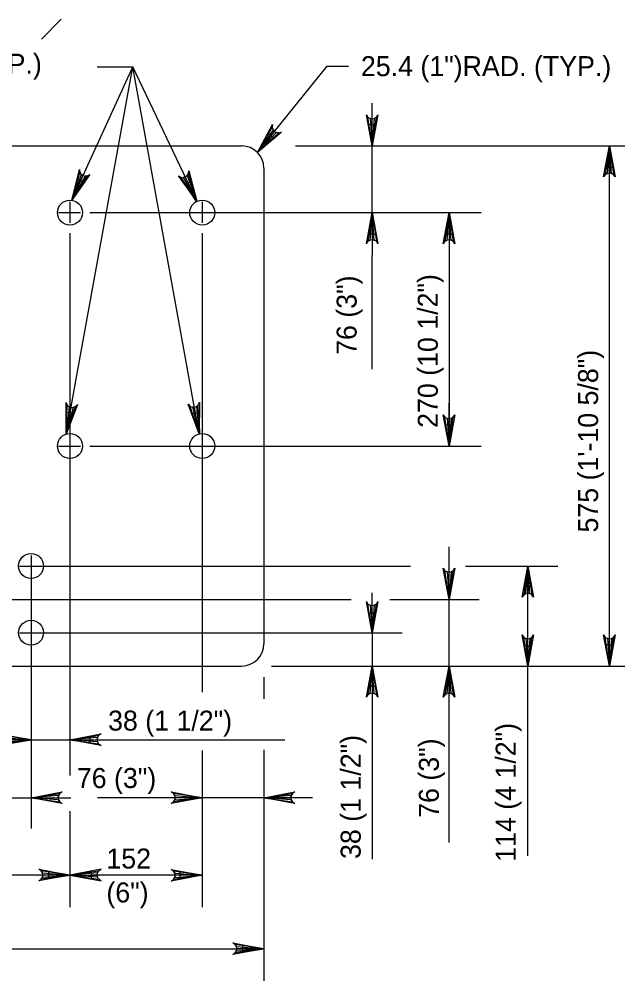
# Model space of a CAD drawing. Extents: x 0 to 36.3, y -66 to 0.
# Drawn here: x 16.77 to 20.36, y -15.09 to -9.32 of the extents above; entities that cross this region are included whole.
import ezdxf

# ---------------------------------------------------------------- set-up
doc = ezdxf.new("R2010")
doc.units = 0
doc.layers.add('2', color=7, linetype='Continuous')
doc.layers.add('3', color=7, linetype='Continuous')

msp = doc.modelspace()

# ---------------------------------------------------------------- linework, layer by layer
at = {"layer": '2'}
for p, q in [((15.0717, -10.0812), (18.1016, -10.0812)), ((18.2348, -10.2145), (18.2348, -13.0677)), ((17.0717, -10.4173), (17.0717, -10.5422)), ((17.865, -10.4173), (17.865, -10.5422)), ((17.0023, -10.4812), (17.1356, -10.4812)), ((17.7956, -10.4812), (17.9289, -10.4812)), ((17.0717, -11.8173), (17.0717, -11.9422)), ((17.865, -11.8173), (17.865, -11.9422)), ((17.0023, -11.8812), (17.1356, -11.8812)), ((17.7956, -11.8812), (17.9289, -11.8812)), ((16.8384, -12.5372), (16.8384, -12.662)), ((16.7691, -12.601), (16.9023, -12.601)), ((16.8384, -12.9372), (16.8384, -13.062)), ((16.7691, -13.001), (16.9023, -13.001))]:
    msp.add_line(p, q, dxfattribs=at)
for centre in [(17.0718, -10.4812), (17.865, -10.4812), (17.0718, -11.8812), (17.865, -11.8812), (16.8385, -12.601), (16.8385, -13.001)]:
    msp.add_circle(centre, 0.075, dxfattribs=at)
for centre, start, end in [((18.1015, -10.2145), 0, 90), ((18.1015, -13.0677), 270, 0)]:
    msp.add_arc(centre, 0.1333, start, end, dxfattribs=at)
at = {"layer": '3'}
for p, q in [((16.9003, -9.4406), (17.0195, -9.3214)), ((17.0498, -11.8094), (17.449, -9.6074)), ((17.0822, -10.4069), (17.449, -9.6074)), ((17.2344, -9.6074), (17.449, -9.6074)), ((17.8336, -10.4131), (17.449, -9.6074)), ((17.8476, -11.8082), (17.449, -9.6074)), ((18.1962, -10.1207), (18.6149, -9.6036)), ((18.6149, -9.6036), (18.743, -9.6036)), ((18.8845, -10.5177), (18.8845, -9.8251)), ((18.4239, -10.0812), (19.0766, -10.0812)), ((18.7894, -10.0812), (20.4997, -10.0812)), ((20.3077, -13.201), (20.3077, -10.0812)), ((17.1916, -10.4812), (19.5383, -10.4812)), ((19.3462, -10.4812), (19.3462, -11.8812)), ((17.0717, -10.6055), (17.0717, -13.8564)), ((17.865, -10.6055), (17.865, -13.3579)), ((18.8845, -10.6092), (18.8845, -10.7373)), ((18.8845, -11.4203), (18.8845, -10.7377)), ((19.3462, -11.7532), (19.3462, -11.6251)), ((17.1916, -11.8812), (19.5383, -11.8812)), ((19.3462, -14.2584), (19.3462, -12.486)), ((16.8384, -12.5522), (16.8384, -14.1747)), ((16.9009, -12.601), (19.1153, -12.601)), ((19.4442, -12.601), (19.9982, -12.601)), ((19.8182, -14.3397), (19.8182, -12.601)), ((16.5009, -12.801), (18.7591, -12.801)), ((18.8845, -13.001), (18.8845, -12.761)), ((18.9901, -12.801), (19.5262, -12.801)), ((16.9009, -13.001), (19.0645, -13.001)), ((18.8845, -13.001), (18.8845, -14.3592)), ((15.0717, -13.201), (18.1016, -13.201)), ((18.2805, -13.201), (19.4821, -13.201)), ((18.2857, -13.201), (19.0645, -13.201)), ((18.967, -13.201), (20.4997, -13.201)), ((19.1593, -13.201), (19.5263, -13.201)), ((19.5628, -13.201), (19.9982, -13.201)), ((18.2348, -13.2684), (18.2348, -13.3984)), ((18.8845, -13.321), (18.8845, -13.441)), ((16.8384, -13.6429), (18.3612, -13.6429)), ((17.1917, -13.6429), (17.3117, -13.6429)), ((17.865, -13.7082), (17.865, -14.6467)), ((18.2348, -13.7037), (18.2348, -15.0885)), ((15.3898, -13.9908), (17.0763, -13.9908)), ((18.5272, -13.9908), (17.2379, -13.9908)), ((17.0717, -14.0719), (17.0717, -14.6467)), ((16.9437, -14.4546), (16.4003, -14.4546)), ((17.73, -14.4546), (17.1998, -14.4546)), ((14.9385, -14.8964), (18.2348, -14.8964))]:
    msp.add_line(p, q, dxfattribs=at)
for points in [[(18.8845, -10.0812), (18.8496, -9.8948), (18.8595, -9.9091), (18.872, -9.9165), (18.8845, -9.9187), (18.897, -9.9165), (18.9095, -9.9091), (18.9194, -9.8948), (18.8845, -10.0812), (18.9095, -9.9091), (18.897, -9.9165), (18.8845, -10.0812), (18.8845, -9.9187), (18.872, -9.9165), (18.8845, -10.0812), (18.8595, -9.9091)], [(18.1962, -10.1207), (18.2863, -9.9538), (18.285, -9.9712), (18.2901, -9.9848), (18.2984, -9.9944), (18.3095, -10.0006), (18.3238, -10.0027), (18.3407, -9.9978), (18.1962, -10.1207), (18.3238, -10.0027), (18.3095, -10.0006), (18.1962, -10.1207), (18.2984, -9.9944), (18.2901, -9.9848), (18.1962, -10.1207), (18.285, -9.9712)], [(20.3077, -10.0812), (20.3426, -10.2676), (20.3327, -10.2532), (20.3202, -10.2458), (20.3077, -10.2437), (20.2952, -10.2458), (20.2827, -10.2532), (20.2727, -10.2676), (20.3077, -10.0812), (20.2827, -10.2532), (20.2952, -10.2458), (20.3077, -10.0812), (20.3077, -10.2437), (20.3202, -10.2458), (20.3077, -10.0812), (20.3327, -10.2532)], [(17.0822, -10.4069), (17.1282, -10.2229), (17.1312, -10.2401), (17.1395, -10.2521), (17.1499, -10.2592), (17.1622, -10.2625), (17.1767, -10.261), (17.1917, -10.2521), (17.0822, -10.4069), (17.1767, -10.261), (17.1622, -10.2625), (17.0822, -10.4069), (17.1499, -10.2592), (17.1395, -10.2521), (17.0822, -10.4069), (17.1312, -10.2401)], [(17.8336, -10.4131), (17.7218, -10.2599), (17.7369, -10.2686), (17.7514, -10.2699), (17.7636, -10.2664), (17.7739, -10.2591), (17.782, -10.2471), (17.7848, -10.2298), (17.8336, -10.4131), (17.782, -10.2471), (17.7739, -10.2591), (17.8336, -10.4131), (17.7636, -10.2664), (17.7514, -10.2699), (17.8336, -10.4131), (17.7369, -10.2686)], [(18.8845, -10.4812), (18.9194, -10.6676), (18.9095, -10.6532), (18.897, -10.6458), (18.8845, -10.6437), (18.872, -10.6458), (18.8595, -10.6532), (18.8496, -10.6676), (18.8845, -10.4812), (18.8595, -10.6532), (18.872, -10.6458), (18.8845, -10.4812), (18.8845, -10.6437), (18.897, -10.6458), (18.8845, -10.4812), (18.9095, -10.6532)], [(19.3462, -10.4812), (19.3812, -10.6676), (19.3712, -10.6532), (19.3588, -10.6458), (19.3462, -10.6437), (19.3337, -10.6458), (19.3212, -10.6532), (19.3113, -10.6676), (19.3462, -10.4812), (19.3212, -10.6532), (19.3337, -10.6458), (19.3462, -10.4812), (19.3462, -10.6437), (19.3588, -10.6458), (19.3462, -10.4812), (19.3712, -10.6532)], [(17.0498, -11.8094), (17.0487, -11.6197), (17.0559, -11.6357), (17.0669, -11.6452), (17.0788, -11.6495), (17.0915, -11.6497), (17.1051, -11.6446), (17.1175, -11.6322), (17.0498, -11.8094), (17.1051, -11.6446), (17.0915, -11.6497), (17.0498, -11.8094), (17.0788, -11.6495), (17.0669, -11.6452), (17.0498, -11.8094), (17.0559, -11.6357)], [(17.8476, -11.8082), (17.78, -11.6311), (17.7923, -11.6434), (17.8059, -11.6485), (17.8186, -11.6483), (17.8306, -11.644), (17.8415, -11.6345), (17.8487, -11.6186), (17.8476, -11.8082), (17.8415, -11.6345), (17.8306, -11.644), (17.8476, -11.8082), (17.8186, -11.6483), (17.8059, -11.6485), (17.8476, -11.8082), (17.7923, -11.6434)], [(19.3462, -11.8812), (19.3113, -11.6947), (19.3212, -11.7091), (19.3337, -11.7165), (19.3462, -11.7187), (19.3588, -11.7165), (19.3712, -11.7091), (19.3812, -11.6947), (19.3462, -11.8812), (19.3712, -11.7091), (19.3588, -11.7165), (19.3462, -11.8812), (19.3462, -11.7187), (19.3337, -11.7165), (19.3462, -11.8812), (19.3212, -11.7091)], [(19.3462, -12.801), (19.3113, -12.6146), (19.3212, -12.6289), (19.3337, -12.6363), (19.3462, -12.6385), (19.3588, -12.6363), (19.3712, -12.6289), (19.3812, -12.6146), (19.3462, -12.801), (19.3712, -12.6289), (19.3588, -12.6363), (19.3462, -12.801), (19.3462, -12.6385), (19.3337, -12.6363), (19.3462, -12.801), (19.3212, -12.6289)], [(19.8182, -12.601), (19.8532, -12.7874), (19.8432, -12.7731), (19.8307, -12.7657), (19.8182, -12.7635), (19.8057, -12.7657), (19.7933, -12.7731), (19.7833, -12.7874), (19.8182, -12.601), (19.7933, -12.7731), (19.8057, -12.7657), (19.8182, -12.601), (19.8182, -12.7635), (19.8307, -12.7657), (19.8182, -12.601), (19.8432, -12.7731)], [(18.8845, -13.001), (18.8496, -12.8146), (18.8595, -12.8289), (18.872, -12.8363), (18.8845, -12.8385), (18.897, -12.8363), (18.9095, -12.8289), (18.9194, -12.8146), (18.8845, -13.001), (18.9095, -12.8289), (18.897, -12.8363), (18.8845, -13.001), (18.8845, -12.8385), (18.872, -12.8363), (18.8845, -13.001), (18.8595, -12.8289)], [(19.8182, -13.201), (19.7833, -13.0146), (19.7933, -13.0289), (19.8057, -13.0363), (19.8182, -13.0385), (19.8307, -13.0363), (19.8432, -13.0289), (19.8532, -13.0146), (19.8182, -13.201), (19.8432, -13.0289), (19.8307, -13.0363), (19.8182, -13.201), (19.8182, -13.0385), (19.8057, -13.0363), (19.8182, -13.201), (19.7933, -13.0289)], [(20.3077, -13.201), (20.2727, -13.0146), (20.2827, -13.0289), (20.2952, -13.0363), (20.3077, -13.0385), (20.3202, -13.0363), (20.3327, -13.0289), (20.3426, -13.0146), (20.3077, -13.201), (20.3327, -13.0289), (20.3202, -13.0363), (20.3077, -13.201), (20.3077, -13.0385), (20.2952, -13.0363), (20.3077, -13.201), (20.2827, -13.0289)], [(18.8845, -13.201), (18.9194, -13.3874), (18.9095, -13.3731), (18.897, -13.3657), (18.8845, -13.3635), (18.872, -13.3657), (18.8595, -13.3731), (18.8496, -13.3874), (18.8845, -13.201), (18.8595, -13.3731), (18.872, -13.3657), (18.8845, -13.201), (18.8845, -13.3635), (18.897, -13.3657), (18.8845, -13.201), (18.9095, -13.3731)], [(19.3462, -13.201), (19.3812, -13.3874), (19.3712, -13.3731), (19.3588, -13.3657), (19.3462, -13.3635), (19.3337, -13.3657), (19.3212, -13.3731), (19.3113, -13.3874), (19.3462, -13.201), (19.3212, -13.3731), (19.3337, -13.3657), (19.3462, -13.201), (19.3462, -13.3635), (19.3588, -13.3657), (19.3462, -13.201), (19.3712, -13.3731)], [(16.8384, -13.6429), (16.652, -13.6778), (16.6663, -13.6679), (16.6737, -13.6554), (16.6759, -13.6429), (16.6737, -13.6304), (16.6663, -13.6179), (16.652, -13.608), (16.8384, -13.6429), (16.6663, -13.6179), (16.6737, -13.6304), (16.8384, -13.6429), (16.6759, -13.6429), (16.6737, -13.6554), (16.8384, -13.6429), (16.6663, -13.6679)], [(17.0717, -13.6429), (17.2582, -13.608), (17.2438, -13.6179), (17.2364, -13.6304), (17.2342, -13.6429), (17.2364, -13.6554), (17.2438, -13.6679), (17.2582, -13.6778), (17.0717, -13.6429), (17.2438, -13.6679), (17.2364, -13.6554), (17.0717, -13.6429), (17.2342, -13.6429), (17.2364, -13.6304), (17.0717, -13.6429), (17.2438, -13.6179)], [(16.8384, -13.9908), (17.0248, -13.9558), (17.0105, -13.9657), (17.0031, -13.9782), (17.0009, -13.9908), (17.0031, -14.0032), (17.0105, -14.0157), (17.0248, -14.0257), (16.8384, -13.9908), (17.0105, -14.0157), (17.0031, -14.0032), (16.8384, -13.9908), (17.0009, -13.9908), (17.0031, -13.9782), (16.8384, -13.9908), (17.0105, -13.9657)], [(17.865, -13.9908), (17.6786, -14.0257), (17.6929, -14.0157), (17.7003, -14.0032), (17.7025, -13.9908), (17.7003, -13.9782), (17.6929, -13.9657), (17.6786, -13.9558), (17.865, -13.9908), (17.6929, -13.9657), (17.7003, -13.9782), (17.865, -13.9908), (17.7025, -13.9908), (17.7003, -14.0032), (17.865, -13.9908), (17.6929, -14.0157)], [(18.2348, -13.9908), (18.4213, -13.9558), (18.4069, -13.9657), (18.3995, -13.9782), (18.3973, -13.9908), (18.3995, -14.0032), (18.4069, -14.0157), (18.4213, -14.0257), (18.2348, -13.9908), (18.4069, -14.0157), (18.3995, -14.0032), (18.2348, -13.9908), (18.3973, -13.9908), (18.3995, -13.9782), (18.2348, -13.9908), (18.4069, -13.9657)], [(17.0717, -14.4546), (16.8853, -14.4895), (16.8997, -14.4796), (16.9071, -14.4671), (16.9093, -14.4546), (16.9071, -14.4421), (16.8997, -14.4296), (16.8853, -14.4197), (17.0717, -14.4546), (16.8997, -14.4296), (16.9071, -14.4421), (17.0717, -14.4546), (16.9093, -14.4546), (16.9071, -14.4671), (17.0717, -14.4546), (16.8997, -14.4796)], [(17.0717, -14.4546), (17.2582, -14.4895), (17.2438, -14.4796), (17.2364, -14.4671), (17.2342, -14.4546), (17.2364, -14.4421), (17.2438, -14.4296), (17.2582, -14.4197), (17.0717, -14.4546), (17.2438, -14.4296), (17.2364, -14.4421), (17.0717, -14.4546), (17.2342, -14.4546), (17.2364, -14.4671), (17.0717, -14.4546), (17.2438, -14.4796)], [(17.865, -14.4558), (17.6786, -14.4907), (17.6929, -14.4807), (17.7003, -14.4682), (17.7025, -14.4558), (17.7003, -14.4432), (17.6929, -14.4307), (17.6786, -14.4208), (17.865, -14.4558), (17.6929, -14.4307), (17.7003, -14.4432), (17.865, -14.4558), (17.7025, -14.4558), (17.7003, -14.4682), (17.865, -14.4558), (17.6929, -14.4807)], [(18.2348, -14.8964), (18.0484, -14.9313), (18.0627, -14.9214), (18.0702, -14.9089), (18.0723, -14.8964), (18.0702, -14.8839), (18.0627, -14.8714), (18.0484, -14.8615), (18.2348, -14.8964), (18.0627, -14.8714), (18.0702, -14.8839), (18.2348, -14.8964), (18.0723, -14.8964), (18.0702, -14.9089), (18.2348, -14.8964), (18.0627, -14.9214)]]:
    msp.add_lwpolyline(points, dxfattribs=at)
for points in [[(18.8631, -9.9532), (18.9058, -9.9532), (18.8845, -10.0812)], [(18.2933, -10.0346), (18.2603, -10.0076), (18.1958, -10.1203)], [(20.2863, -10.2092), (20.329, -10.2092), (20.3077, -10.0812)], [(17.155, -10.2993), (17.1162, -10.2816), (17.0824, -10.4069)], [(17.7998, -10.2927), (17.7606, -10.3096), (17.831, -10.4187)], [(18.8631, -10.6092), (18.9058, -10.6092), (18.8845, -10.4812)], [(19.3249, -10.6092), (19.3676, -10.6092), (19.3462, -10.4812)], [(17.0938, -11.6865), (17.0517, -11.6792), (17.051, -11.8091)], [(17.846, -11.6799), (17.8041, -11.6883), (17.8502, -11.8097)], [(19.3249, -11.7532), (19.3676, -11.7532), (19.3462, -11.8812)], [(19.7982, -12.721), (19.8382, -12.721), (19.8182, -12.601)], [(18.8645, -12.881), (18.9045, -12.881), (18.8845, -13.001)], [(19.7982, -13.081), (19.8382, -13.081), (19.8182, -13.201)], [(20.2863, -13.0729), (20.329, -13.0729), (20.3077, -13.201)], [(18.8645, -13.321), (18.9045, -13.321), (18.8845, -13.201)], [(16.7184, -13.6229), (16.7184, -13.6629), (16.8384, -13.6429)], [(17.1917, -13.6229), (17.1917, -13.6629), (17.0717, -13.6429)], [(16.9437, -14.4332), (16.9437, -14.4759), (17.0717, -14.4546)], [(17.1998, -14.4332), (17.1998, -14.4759), (17.0717, -14.4546)], [(17.73, -14.4332), (17.73, -14.4759), (17.858, -14.4546)], [(18.1067, -14.8751), (18.1067, -14.9177), (18.2348, -14.8964)]]:
    msp.add_lwpolyline(points, close=True, dxfattribs=at)

# ---------------------------------------------------------------- texts
for s, p in [('HOLES (TYP.)', (15.8508, -9.6487)), ('25.4 (1")RAD. (TYP.)', (18.8171, -9.6629)), ('38 (1 1/2")', (17.3004, -13.5881)), ('76 (3")', (17.113, -13.9325)), ('152', (17.2904, -14.4153)), ('(6")', (17.2904, -14.6187))]:
    msp.add_text(s, height=0.12, dxfattribs=at).set_placement(p)
for s, p in [('76 (3")', (18.7914, -11.3345)), ('270 (10 1/2")', (19.2782, -11.7725)), ('575 (1\'-10 5/8")', (20.2397, -12.4)), ('114 (4 1/2")', (19.7454, -14.3752)), ('38 (1 1/2")', (18.8156, -14.358)), ('76 (3")', (19.2846, -14.1112))]:
    msp.add_text(s, height=0.12, rotation=90, dxfattribs=at).set_placement(p)

doc.saveas('drawing.dxf')
